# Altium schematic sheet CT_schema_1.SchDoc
size 457 x 258 mm
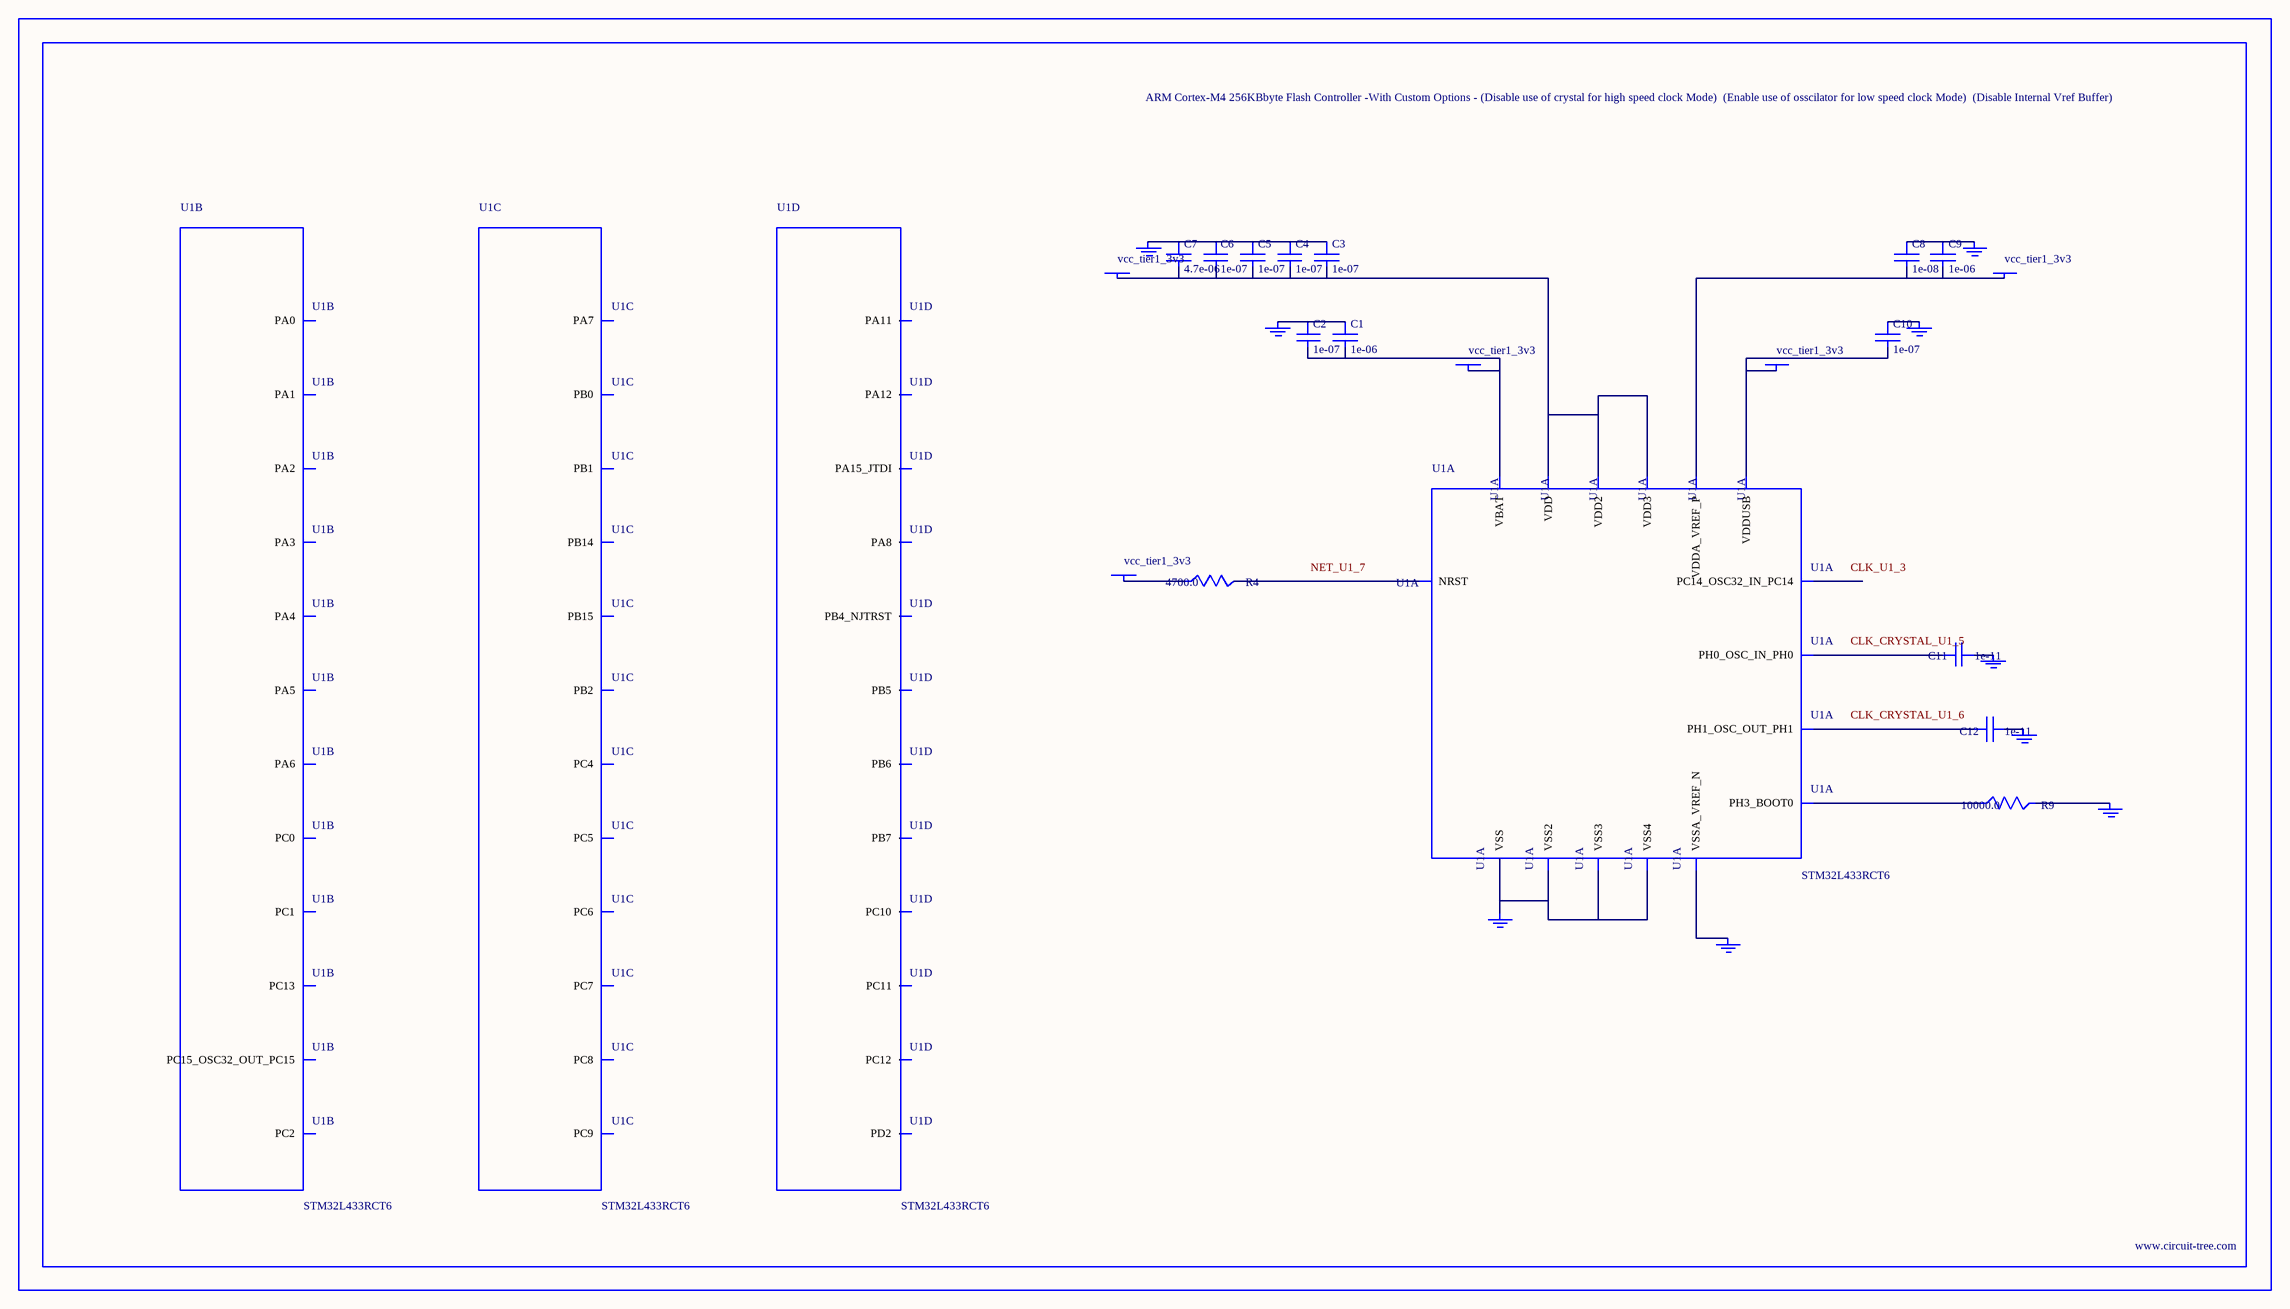
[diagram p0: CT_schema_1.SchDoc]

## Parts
BORDER0  (no value)
C1  1e-06  [C0603]
C2  1e-07  [C0603]
C3  1e-07  [C0603]
C4  1e-07  [C0603]
C5  1e-07  [C0603]
C6  1e-07  [C0603]
C7  4.7e-06  [C0603]
C8  1e-08  [C0603]
C9  1e-06  [C0603]
C10  1e-07  [C0603]
C11  1e-11  [C0402]
C12  1e-11  [C0402]
GND_INSTANCE_0_0  (no value)
GND_INSTANCE_0_1  (no value)
GND_INSTANCE_0_2  (no value)
GND_INSTANCE_0_3  (no value)
GND_INSTANCE_0_4  (no value)
GND_INSTANCE_0_5  (no value)
GND_INSTANCE_0_6  (no value)
GND_INSTANCE_0_7  (no value)
GND_INSTANCE_0_8  (no value)
POWER_INSTANCE_0_0  vcc_tier1_3v3
POWER_INSTANCE_0_1  vcc_tier1_3v3
POWER_INSTANCE_0_2  vcc_tier1_3v3
POWER_INSTANCE_0_3  vcc_tier1_3v3
POWER_INSTANCE_0_4  vcc_tier1_3v3
R4  4700.0  [R0603]
R9  10000.0  [R0603]
U1  STM32L433RCT6  [LQFP64]  (parts A,B,C,D of 8)

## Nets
NetC1_1: C1.1 C2.1 GND_INSTANCE_0_0.0(GND)
NetC1_2: C1.2 C2.2 POWER_INSTANCE_0_0.0(PWR) U1.1(VBAT)
NetC3_1: C3.1 C4.1 C5.1 C6.1 C7.1 GND_INSTANCE_0_5.0(GND)
NetC3_2: C3.2 C4.2 C5.2 C6.2 C7.2 POWER_INSTANCE_0_2.0(PWR) U1.19(VDD) U1.32(VDD2) U1.64(VDD3)
NetC8_1: C8.1 C9.1 GND_INSTANCE_0_4.0(GND)
NetC8_2: C8.2 C9.2 POWER_INSTANCE_0_1.0(PWR) U1.13(VDDA_VREF_P)
NetC10_1: C10.1 GND_INSTANCE_0_6.0(GND)
NetC10_2: C10.2 POWER_INSTANCE_0_3.0(PWR) U1.48(VDDUSB)
NetC11_1: C11.1 GND_INSTANCE_0_1.0(GND)
NetC11_2: C11.2 U1.5(PH0_OSC_IN_PH0)
NetC12_1: C12.1 GND_INSTANCE_0_2.0(GND)
NetC12_2: C12.2 U1.6(PH1_OSC_OUT_PH1)
NetGND_INSTANCE_0_3_0: GND_INSTANCE_0_3.0(GND) U1.12(VSSA_VREF_N)
NetGND_INSTANCE_0_7_0: GND_INSTANCE_0_7.0(GND) R9.2
NetGND_INSTANCE_0_8_0: GND_INSTANCE_0_8.0(GND) U1.18(VSS) U1.31(VSS2) U1.47(VSS3) U1.63(VSS4)
NetPOWER_INSTANCE_0_4_0: POWER_INSTANCE_0_4.0(PWR) R4.1
NetR4_2: R4.2 U1.7(NRST)
NetR9_1: R9.1 U1.60(PH3_BOOT0)

Not connected (* = marked no-connect by the designer): U1 2(PC13) 3(PC14_OSC32_IN_PC14) 4(PC15_OSC32_OUT_PC15) 8(PC0) 9(PC1) 10(PC2) 14(PA0) 15(PA1) 16(PA2) 17(PA3) 20(PA4) 21(PA5) 22(PA6) 23(PA7) 24(PC4) 25(PC5) 26(PB0) 27(PB1) 28(PB2) 35(PB14) 36(PB15) 37(PC6) 38(PC7) 39(PC8) 40(PC9) 41(PA8) 44(PA11) 45(PA12) 50(PA15_JTDI) 51(PC10) 52(PC11) 53(PC12) 54(PD2) 56(PB4_NJTRST) 57(PB5) 58(PB6) 59(PB7)

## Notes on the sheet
- Labels drawn without touching a wire or pin: CLK_CRYSTAL_U1_5, CLK_CRYSTAL_U1_6, CLK_U1_3, NET_U1_7

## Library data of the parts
BORDER0 = BORDER_PAGE0
C1 C9 = C0603C105K3RACTU
C2-C6 C10 = 06035C104K4Z2A
C7 = GRM188R6YA475KE15D
C8 = 06035C103K4Z2A
C11 C12 = C0402C100K3GACTU
GND_INSTANCE_0_0-GND_INSTANCE_0_8 = GND
POWER_INSTANCE_0_0-POWER_INSTANCE_0_4 = PWR
R4 = RC0603JR-074K7L
R9 = RC0603JR-0710KL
